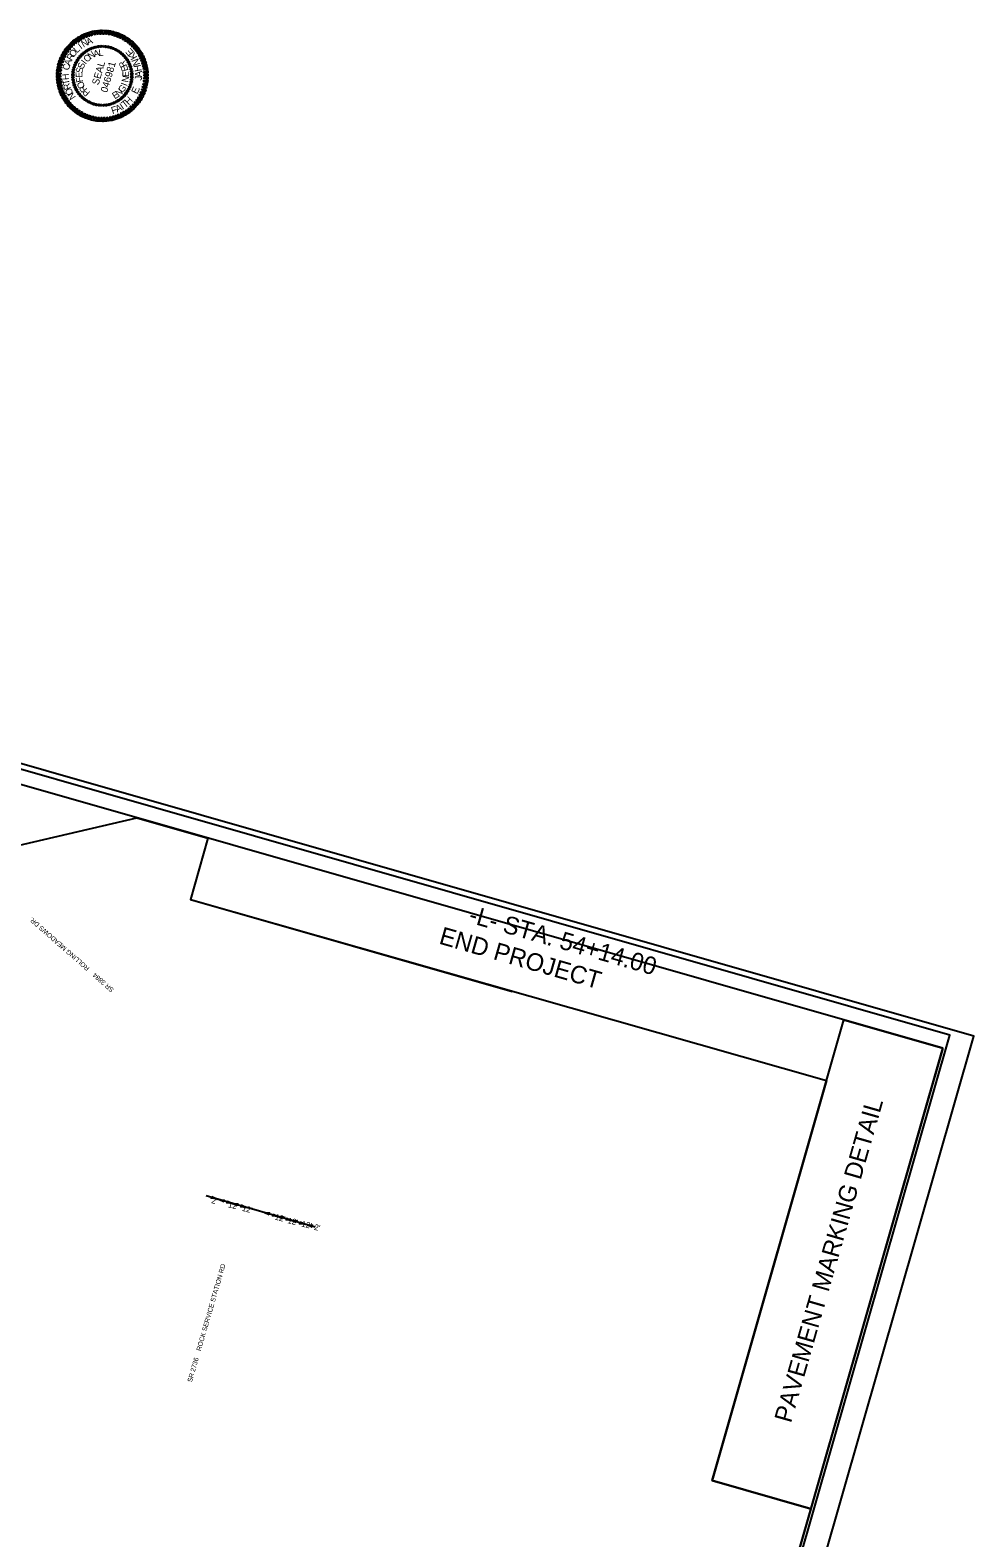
# Model space of a CAD drawing. Extents: x 2096990 to 2098506, y 687712 to 690186.
# Drawn here: x 2097704 to 2098506, y 688904 to 690186 of the extents above; entities that cross this region are included whole.
import ezdxf

# ---------------------------------------------------------------- set-up
doc = ezdxf.new("R2010")
doc.units = 0
for name, color, linetype in [('Default', 7, 'Continuous'), ('Matchline', 7, 'Continuous'), ('Matchline Text', 7, 'Continuous'), ('Sheet Layout Plan Border', 7, 'Continuous'), ('Sheet PE Seal Cell', 7, 'Continuous'), ('Sheet Plan CELL', 7, 'Continuous'), ('Sheet Plot Border Inside CELL', 7, 'Continuous'), ('Sheet Plot Border Outside CELL', 7, 'Continuous'), ('Text', 7, 'Continuous')]:
    doc.layers.add(name, color=color, linetype=linetype)

msp = doc.modelspace()

# ---------------------------------------------------------------- linework, layer by layer
at = {"layer": 'Default'}
msp.add_line((2097946.4, 689168), (2097853.6, 689194.6), dxfattribs=at)
for points in [[(2097858.4, 689194), (2097862.5, 689192), (2097858, 689192.5), (2097858.7, 689193.1)], [(2097868.6, 689189.4), (2097864.5, 689191.4), (2097869.1, 689191), (2097868.3, 689190.3)], [(2097871.9, 689190.1), (2097876, 689188.1), (2097871.4, 689188.6), (2097872.2, 689189.2)], [(2097880.1, 689186.2), (2097876, 689188.1), (2097880.6, 689187.7), (2097879.8, 689187.1)], [(2097883.6, 689186.8), (2097887.7, 689184.8), (2097883.1, 689185.3), (2097883.9, 689185.9)], [(2097907.2, 689178.5), (2097903.1, 689180.5), (2097907.6, 689180), (2097906.9, 689179.4)], [(2097910.6, 689179.1), (2097914.7, 689177.1), (2097910.2, 689177.6), (2097910.9, 689178.2)], [(2097918.7, 689175.1), (2097914.6, 689177.1), (2097919.2, 689176.6), (2097918.4, 689176)], [(2097922.1, 689175.7), (2097926.3, 689173.7), (2097921.7, 689174.2), (2097922.5, 689174.8)], [(2097930.2, 689171.8), (2097926.1, 689173.8), (2097930.7, 689173.3), (2097929.9, 689172.7)], [(2097933.7, 689172.4), (2097937.8, 689170.4), (2097933.2, 689170.9), (2097934, 689171.5)], [(2097943.7, 689168), (2097939.6, 689169.9), (2097944.2, 689169.5), (2097943.4, 689168.9)]]:
    msp.add_lwpolyline(points, close=True, dxfattribs=at)
at = {"layer": 'Matchline'}
msp.add_line((2097840.3, 689446.6), (2098113.9, 689368.3), dxfattribs=at)
at = {"layer": 'Sheet Layout Plan Border'}
msp.add_lwpolyline([(2098367.9, 688928.4), (2098117.8, 688054.5), (2097561.3, 688075.8), (2097494.5, 688123.8), (2097678.9, 688821), (2097441.6, 689082.4), (2097413, 689407.6), (2097643.8, 689341.5), (2097686.6, 689490.9), (2097794.8, 689516.3), (2097855.1, 689499), (2097840.3, 689446.6), (2098381.2, 689292.7), (2098283.8, 688952.5)], close=True, dxfattribs=at)
at = {"layer": 'Sheet PE Seal Cell'}
for p, q in [((2097748.3, 690165.8), (2097748.3, 690165.8)), ((2097750, 690167.2), (2097750, 690167.2)), ((2097751.8, 690168.5), (2097751.8, 690168.5)), ((2097753.6, 690169.6), (2097753.6, 690169.6)), ((2097755.6, 690170.6), (2097755.6, 690170.6)), ((2097757.6, 690171.3), (2097757.6, 690171.3)), ((2097759.8, 690171.9), (2097759.8, 690171.9)), ((2097761.9, 690172.3), (2097761.9, 690172.3)), ((2097764.1, 690172.5), (2097764.1, 690172.5)), ((2097766.3, 690172.5), (2097766.3, 690172.5)), ((2097768.5, 690172.3), (2097768.5, 690172.3)), ((2097770.6, 690172), (2097770.6, 690172)), ((2097772.8, 690171.5), (2097772.8, 690171.5)), ((2097774.8, 690170.7), (2097774.8, 690170.7)), ((2097776.8, 690169.8), (2097776.8, 690169.8)), ((2097778.7, 690168.8), (2097778.7, 690168.8)), ((2097780.5, 690167.5), (2097780.5, 690167.5)), ((2097782.2, 690166.1), (2097782.2, 690166.1)), ((2097783.8, 690164.6), (2097783.8, 690164.6)), ((2097740.9, 690152.7), (2097740.9, 690152.7)), ((2097741.4, 690154.8), (2097741.4, 690154.8)), ((2097742.2, 690156.9), (2097742.2, 690156.9)), ((2097743.1, 690158.8), (2097743.1, 690158.8)), ((2097744.1, 690160.7), (2097744.1, 690160.7)), ((2097745.4, 690162.6), (2097745.4, 690162.6)), ((2097746.8, 690164.2), (2097746.8, 690164.2)), ((2097785.2, 690162.9), (2097785.2, 690162.9)), ((2097786.5, 690161.1), (2097786.5, 690161.1)), ((2097787.6, 690159.3), (2097787.6, 690159.3)), ((2097788.6, 690157.3), (2097788.6, 690157.3)), ((2097789.3, 690155.2), (2097789.3, 690155.2)), ((2097789.9, 690153.1), (2097789.9, 690153.1)), ((2097740.3, 690148.3), (2097740.3, 690148.3)), ((2097740.3, 690146.1), (2097740.3, 690146.1)), ((2097740.6, 690150.5), (2097740.6, 690150.5)), ((2097740.6, 690144), (2097740.6, 690144)), ((2097741, 690141.8), (2097741, 690141.8)), ((2097741.6, 690139.7), (2097741.6, 690139.7)), ((2097765.4, 690147.5), (2097765.4, 690147.5)), ((2097789.4, 690140.1), (2097789.4, 690140.1)), ((2097790, 690142.2), (2097790, 690142.2)), ((2097790.3, 690150.9), (2097790.3, 690150.9)), ((2097790.3, 690144.4), (2097790.3, 690144.4)), ((2097790.5, 690148.8), (2097790.5, 690148.8)), ((2097790.5, 690146.6), (2097790.5, 690146.6)), ((2097742.3, 690137.6), (2097742.3, 690137.6)), ((2097743.3, 690135.6), (2097743.3, 690135.6)), ((2097744.4, 690133.8), (2097744.4, 690133.8)), ((2097745.7, 690132), (2097745.7, 690132)), ((2097747.1, 690130.3), (2097747.1, 690130.3)), ((2097748.7, 690128.8), (2097748.7, 690128.8)), ((2097750.3, 690127.4), (2097750.3, 690127.4)), ((2097752.2, 690126.1), (2097752.2, 690126.1)), ((2097779.1, 690126.4), (2097779.1, 690126.4)), ((2097780.9, 690127.7), (2097780.9, 690127.7)), ((2097782.6, 690129.1), (2097782.6, 690129.1)), ((2097784.1, 690130.7), (2097784.1, 690130.7)), ((2097785.5, 690132.3), (2097785.5, 690132.3)), ((2097786.8, 690134.2), (2097786.8, 690134.2)), ((2097787.8, 690136.1), (2097787.8, 690136.1)), ((2097788.7, 690138), (2097788.7, 690138)), ((2097754, 690125.1), (2097754, 690125.1)), ((2097756, 690124.2), (2097756, 690124.2)), ((2097758.1, 690123.4), (2097758.1, 690123.4)), ((2097760.2, 690122.9), (2097760.2, 690122.9)), ((2097762.4, 690122.6), (2097762.4, 690122.6)), ((2097764.6, 690122.4), (2097764.6, 690122.4)), ((2097766.8, 690122.4), (2097766.8, 690122.4)), ((2097768.9, 690122.6), (2097768.9, 690122.6)), ((2097771.1, 690123), (2097771.1, 690123)), ((2097773.2, 690123.6), (2097773.2, 690123.6)), ((2097775.2, 690124.3), (2097775.2, 690124.3)), ((2097777.2, 690125.3), (2097777.2, 690125.3))]:
    msp.add_line(p, q, dxfattribs=at)
for points in [[(2097742.6, 690174.6), (2097740.3, 690177.1), (2097741.7, 690178), (2097743.5, 690175.5)], [(2097744.6, 690176.1), (2097742.5, 690178.7), (2097743.9, 690179.6), (2097745.6, 690176.9)], [(2097746.6, 690177.5), (2097744.7, 690180.2), (2097746.2, 690181), (2097747.6, 690178.2)], [(2097748.8, 690178.8), (2097747.1, 690181.5), (2097748.6, 690182.3), (2097749.8, 690179.3)], [(2097751, 690180), (2097749.5, 690182.8), (2097751.1, 690183.4), (2097752.2, 690180.4)], [(2097753.3, 690180.9), (2097752, 690183.8), (2097753.6, 690184.3), (2097754.4, 690181.2)], [(2097755.6, 690181.6), (2097754.5, 690184.6), (2097756.2, 690185.1), (2097756.8, 690182)], [(2097758.1, 690182.2), (2097757.2, 690185.4), (2097758.9, 690185.6), (2097759.2, 690182.5)], [(2097760.5, 690182.6), (2097759.8, 690185.8), (2097761.5, 690186), (2097761.7, 690182.8)], [(2097763, 690182.8), (2097762.6, 690186.1), (2097764.2, 690186.2), (2097764.1, 690183)], [(2097765.5, 690182.9), (2097765.3, 690186.3), (2097766.9, 690186.1), (2097766.6, 690183)], [(2097768, 690182.8), (2097767.9, 690186.1), (2097769.6, 690185.9), (2097769.1, 690182.8)], [(2097770.4, 690182.6), (2097770.6, 690185.9), (2097772.3, 690185.6), (2097771.6, 690182.5)], [(2097772.8, 690182.2), (2097773.3, 690185.5), (2097775, 690185.1), (2097774, 690182)], [(2097775.2, 690181.6), (2097776, 690184.7), (2097777.6, 690184.3), (2097776.4, 690181.2)], [(2097777.6, 690180.8), (2097778.6, 690183.9), (2097780.1, 690183.4), (2097778.7, 690180.4)], [(2097779.8, 690179.9), (2097781, 690182.9), (2097782.6, 690182.3), (2097780.9, 690179.4)], [(2097782.2, 690178.9), (2097783.4, 690181.7), (2097784.9, 690180.9), (2097783.1, 690178.2)], [(2097784.3, 690177.6), (2097785.8, 690180.4), (2097787.3, 690179.6), (2097785.2, 690176.9)], [(2097786.4, 690176.2), (2097788.1, 690178.9), (2097789.4, 690177.9), (2097787.3, 690175.4)], [(2097733.5, 690162.9), (2097730.6, 690164.2), (2097731.3, 690165.8), (2097734, 690164)], [(2097734.7, 690165.2), (2097731.8, 690166.6), (2097732.6, 690168.1), (2097735.3, 690166.2)], [(2097736, 690167.4), (2097733.3, 690168.9), (2097734.2, 690170.3), (2097736.7, 690168.3)], [(2097737.5, 690169.3), (2097734.8, 690171.2), (2097735.8, 690172.4), (2097738.2, 690170.3)], [(2097739, 690171.2), (2097736.6, 690173.2), (2097737.7, 690174.5), (2097739.9, 690172.1)], [(2097740.8, 690173.1), (2097738.4, 690175.2), (2097739.6, 690176.4), (2097741.6, 690173.8)], [(2097788.2, 690174.6), (2097790.2, 690177.3), (2097791.5, 690176.1), (2097789.2, 690173.8)], [(2097790.2, 690173), (2097792.2, 690175.4), (2097793.4, 690174.3), (2097790.9, 690172.2)], [(2097791.9, 690171.3), (2097794.1, 690173.6), (2097795.2, 690172.2), (2097792.6, 690170.3)], [(2097793.4, 690169.3), (2097795.8, 690171.4), (2097796.9, 690170.1), (2097794.2, 690168.4)], [(2097794.8, 690167.3), (2097797.4, 690169.3), (2097798.4, 690167.9), (2097795.5, 690166.4)], [(2097796.2, 690165.1), (2097798.9, 690167), (2097799.6, 690165.5), (2097796.7, 690164.1)], [(2097797.4, 690163.1), (2097800.1, 690164.6), (2097801, 690163.1), (2097797.8, 690161.9)], [(2097730.1, 690151.2), (2097726.8, 690151.3), (2097727.1, 690153), (2097730.3, 690152.4)], [(2097730.5, 690153.6), (2097727.2, 690154), (2097727.5, 690155.6), (2097730.7, 690154.8)], [(2097730.9, 690156.1), (2097727.7, 690156.7), (2097728.2, 690158.3), (2097731.3, 690157.2)], [(2097731.6, 690158.4), (2097728.5, 690159.3), (2097729, 690160.8), (2097732, 690159.5)], [(2097732.5, 690160.7), (2097729.4, 690161.8), (2097730.1, 690163.3), (2097733, 690161.8)], [(2097798.3, 690160.7), (2097801.2, 690162.1), (2097801.9, 690160.5), (2097798.7, 690159.6)], [(2097799.3, 690158.5), (2097802.2, 690159.5), (2097802.8, 690158), (2097799.5, 690157.2)], [(2097799.9, 690156), (2097803, 690157), (2097803.3, 690155.3), (2097800.2, 690154.9)], [(2097800.4, 690153.6), (2097803.6, 690154.4), (2097803.8, 690152.7), (2097800.6, 690152.4)], [(2097730, 690148.8), (2097726.7, 690148.6), (2097726.8, 690150.3), (2097730, 690149.8)], [(2097729.9, 690146.3), (2097726.7, 690146), (2097726.7, 690147.6), (2097729.9, 690147.4)], [(2097730, 690143.7), (2097726.9, 690143.2), (2097726.7, 690144.9), (2097730.1, 690145)], [(2097730.4, 690141.3), (2097727.3, 690140.5), (2097727.1, 690142.2), (2097730.3, 690142.5)], [(2097731, 690138.9), (2097727.9, 690137.9), (2097727.6, 690139.6), (2097730.7, 690140)], [(2097800.4, 690141.3), (2097803.6, 690140.9), (2097803.3, 690139.3), (2097800.2, 690140.1)], [(2097800.8, 690143.7), (2097804.1, 690143.6), (2097803.7, 690141.9), (2097800.6, 690142.5)], [(2097800.8, 690151.2), (2097804, 690151.7), (2097804.1, 690150), (2097800.8, 690149.9)], [(2097800.9, 690146.1), (2097804.2, 690146.3), (2097804.1, 690144.6), (2097800.8, 690145.1)], [(2097800.9, 690148.6), (2097804.1, 690148.9), (2097804.1, 690147.3), (2097801, 690147.5)], [(2097731.6, 690136.4), (2097728.6, 690135.4), (2097728.1, 690136.9), (2097731.3, 690137.7)], [(2097732.5, 690134.2), (2097729.6, 690132.8), (2097729, 690134.4), (2097732.2, 690135.3)], [(2097733.5, 690131.8), (2097730.7, 690130.3), (2097729.9, 690131.8), (2097733, 690133)], [(2097734.7, 690129.8), (2097732, 690127.9), (2097731.2, 690129.4), (2097734.1, 690130.8)], [(2097736, 690127.6), (2097733.4, 690125.6), (2097732.5, 690127), (2097735.4, 690128.5)], [(2097737.4, 690125.6), (2097735.1, 690123.5), (2097733.9, 690124.8), (2097736.7, 690126.5)], [(2097794.8, 690127.5), (2097797.6, 690126), (2097796.7, 690124.6), (2097794.2, 690126.6)], [(2097796.1, 690129.7), (2097799.1, 690128.3), (2097798.3, 690126.8), (2097795.6, 690128.7)], [(2097797.4, 690132), (2097800.3, 690130.7), (2097799.6, 690129.1), (2097796.9, 690130.9)], [(2097798.4, 690134.2), (2097801.5, 690133.1), (2097800.7, 690131.6), (2097797.9, 690133.1)], [(2097799.2, 690136.5), (2097802.4, 690135.6), (2097801.9, 690134.1), (2097798.9, 690135.4)], [(2097799.9, 690138.8), (2097803.1, 690138.2), (2097802.6, 690136.6), (2097799.6, 690137.7)], [(2097739, 690123.6), (2097736.7, 690121.3), (2097735.7, 690122.7), (2097738.3, 690124.6)], [(2097740.7, 690121.9), (2097738.7, 690119.5), (2097737.4, 690120.6), (2097739.9, 690122.7)], [(2097742.6, 690120.3), (2097740.7, 690117.6), (2097739.4, 690118.8), (2097741.7, 690121.1)], [(2097744.5, 690118.7), (2097742.7, 690116), (2097741.4, 690117), (2097743.6, 690119.5)], [(2097746.6, 690117.3), (2097745.1, 690114.5), (2097743.6, 690115.3), (2097745.7, 690118)], [(2097748.7, 690116), (2097747.5, 690113.2), (2097745.9, 690114), (2097747.8, 690116.7)], [(2097751, 690115), (2097749.9, 690112), (2097748.3, 690112.6), (2097749.9, 690115.5)], [(2097753.3, 690114.1), (2097752.3, 690111), (2097750.7, 690111.5), (2097752.1, 690114.5)], [(2097755.7, 690113.3), (2097754.9, 690110.2), (2097753.3, 690110.6), (2097754.5, 690113.7)], [(2097775.2, 690113.3), (2097776.3, 690110.3), (2097774.6, 690109.8), (2097774.1, 690112.9)], [(2097777.6, 690114), (2097778.9, 690111.1), (2097777.2, 690110.6), (2097776.5, 690113.7)], [(2097779.8, 690114.9), (2097781.4, 690112.1), (2097779.8, 690111.5), (2097778.7, 690114.5)], [(2097782.1, 690116.1), (2097783.7, 690113.4), (2097782.2, 690112.6), (2097781.1, 690115.6)], [(2097784.2, 690117.4), (2097786.2, 690114.7), (2097784.7, 690113.9), (2097783.2, 690116.7)], [(2097786.2, 690118.8), (2097788.4, 690116.2), (2097787, 690115.3), (2097785.3, 690118)], [(2097788.2, 690120.3), (2097790.6, 690117.8), (2097789.2, 690116.9), (2097787.4, 690119.4)], [(2097790.1, 690121.8), (2097792.5, 690119.7), (2097791.2, 690118.5), (2097789.2, 690121.1)], [(2097791.8, 690123.7), (2097794.3, 690121.7), (2097793.2, 690120.4), (2097791, 690122.8)], [(2097793.4, 690125.6), (2097796.1, 690123.7), (2097795.1, 690122.5), (2097792.7, 690124.6)], [(2097758.1, 690112.7), (2097757.6, 690109.4), (2097755.9, 690109.8), (2097756.9, 690112.9)], [(2097760.5, 690112.3), (2097760.2, 690109), (2097758.6, 690109.3), (2097759.3, 690112.4)], [(2097762.9, 690112.1), (2097762.9, 690108.8), (2097761.2, 690109), (2097761.8, 690112.1)], [(2097765.4, 690112), (2097765.6, 690108.6), (2097763.9, 690108.8), (2097764.3, 690111.9)], [(2097767.9, 690112.1), (2097768.3, 690108.8), (2097766.7, 690108.7), (2097766.8, 690111.9)], [(2097770.4, 690112.3), (2097771, 690109.1), (2097769.3, 690108.9), (2097769.2, 690112.1)], [(2097772.7, 690112.7), (2097773.7, 690109.5), (2097772, 690109.3), (2097771.7, 690112.4)]]:
    msp.add_lwpolyline(points, close=True, dxfattribs=at)
for centre, major_axis in [((2097746.8, 690164.2), (-0.535, 0.482)), ((2097748.3, 690165.8), (-0.491, 0.526)), ((2097750, 690167.2), (-0.444, 0.567)), ((2097751.8, 690168.5), (-0.392, 0.604)), ((2097753.6, 690169.6), (-0.338, 0.636)), ((2097755.6, 690170.5), (-0.282, 0.663)), ((2097757.7, 690171.3), (-0.223, 0.685)), ((2097759.8, 690171.9), (-0.162, 0.701)), ((2097761.9, 690172.3), (-0.101, 0.713)), ((2097764.1, 690172.5), (-0.038, 0.719)), ((2097766.3, 690172.5), (0.025, 0.72)), ((2097768.5, 690172.3), (0.087, 0.715)), ((2097770.6, 690172), (0.149, 0.704)), ((2097772.8, 690171.4), (0.21, 0.689)), ((2097774.8, 690170.7), (0.269, 0.668)), ((2097776.8, 690169.8), (0.327, 0.642)), ((2097778.7, 690168.7), (0.381, 0.611)), ((2097780.5, 690167.5), (0.433, 0.575)), ((2097782.2, 690166.1), (0.482, 0.535)), ((2097783.8, 690164.6), (0.526, 0.491)), ((2097740.9, 690152.7), (-0.704, 0.149)), ((2097741.4, 690154.8), (-0.689, 0.21)), ((2097742.2, 690156.8), (-0.668, 0.269)), ((2097743.1, 690158.8), (-0.642, 0.327)), ((2097744.2, 690160.7), (-0.611, 0.381)), ((2097745.4, 690162.5), (-0.575, 0.433)), ((2097785.2, 690162.9), (0.567, 0.444)), ((2097786.5, 690161.1), (0.604, 0.392)), ((2097787.6, 690159.2), (0.636, 0.338)), ((2097788.5, 690157.3), (0.663, 0.282)), ((2097789.3, 690155.2), (0.685, 0.223)), ((2097789.9, 690153.1), (0.701, 0.162)), ((2097790.3, 690151), (0.713, 0.101)), ((2097740.4, 690148.3), (-0.72, 0.025)), ((2097740.4, 690146.1), (-0.719, -0.038)), ((2097740.5, 690150.5), (-0.715, 0.087)), ((2097740.6, 690143.9), (-0.713, -0.101)), ((2097741, 690141.8), (-0.701, -0.162)), ((2097741.6, 690139.7), (-0.685, -0.223)), ((2097788.7, 690138.1), (0.668, -0.269)), ((2097789.4, 690140.1), (0.689, -0.21)), ((2097790, 690142.2), (0.704, -0.149)), ((2097790.3, 690144.4), (0.715, -0.087)), ((2097790.5, 690148.8), (0.719, 0.038)), ((2097790.5, 690146.6), (0.72, -0.025)), ((2097742.3, 690137.6), (-0.663, -0.282)), ((2097743.3, 690135.7), (-0.636, -0.338)), ((2097744.4, 690133.8), (-0.604, -0.392)), ((2097745.7, 690132), (-0.567, -0.444)), ((2097747.1, 690130.3), (-0.526, -0.491)), ((2097748.7, 690128.8), (-0.482, -0.535)), ((2097750.3, 690127.4), (-0.433, -0.575)), ((2097752.2, 690126.2), (-0.381, -0.611)), ((2097777.2, 690125.3), (0.338, -0.636)), ((2097779.1, 690126.4), (0.392, -0.604)), ((2097780.9, 690127.7), (0.444, -0.567)), ((2097782.5, 690129.1), (0.491, -0.526)), ((2097784.1, 690130.7), (0.535, -0.482)), ((2097785.5, 690132.4), (0.575, -0.433)), ((2097786.7, 690134.2), (0.611, -0.381)), ((2097787.8, 690136.1), (0.642, -0.327)), ((2097754.1, 690125.1), (-0.327, -0.642)), ((2097756, 690124.2), (-0.269, -0.668)), ((2097758.1, 690123.5), (-0.21, -0.689)), ((2097760.2, 690122.9), (-0.149, -0.704)), ((2097762.4, 690122.6), (-0.087, -0.715)), ((2097764.6, 690122.4), (-0.025, -0.72)), ((2097766.8, 690122.4), (0.038, -0.719)), ((2097768.9, 690122.6), (0.101, -0.713)), ((2097771.1, 690123), (0.162, -0.701)), ((2097773.2, 690123.6), (0.223, -0.685)), ((2097775.2, 690124.4), (0.282, -0.663))]:
    msp.add_ellipse(centre, major_axis=major_axis, ratio=0.999708, dxfattribs=at)
at = {"layer": 'Sheet Plan CELL'}
for p, q in [((2098480.1, 689320.1), (2097470.6, 689609.1)), ((2098067.3, 687878), (2098480.1, 689320.1))]:
    msp.add_line(p, q, dxfattribs=at)
msp.add_lwpolyline([(2098480.1, 689320.1), (2098367.9, 688928.4), (2098283.8, 688952.5), (2098396, 689344.2)], close=True, dxfattribs=at)
at = {"layer": 'Sheet Plot Border Inside CELL'}
msp.add_lwpolyline([(2098027.5, 687729.8), (2098485.9, 689331.4), (2097471.7, 689621.8), (2097013.2, 688020.1)], close=True, dxfattribs=at)
at = {"layer": 'Sheet Plot Border Outside CELL'}
msp.add_lwpolyline([(2098043.1, 687711.8), (2098506.4, 689330.3), (2097453.7, 689631.6), (2096990.4, 688013.1)], close=True, dxfattribs=at)

# ---------------------------------------------------------------- texts
at = {"layer": 'Matchline Text'}
for s, p in [('-L- STA. 54+14.00', (2098076, 689427.4)), ('END PROJECT', (2098050.9, 689409.3))]:
    msp.add_text(s, height=15, rotation=343.9917, dxfattribs=at).set_placement(p)
at = {"layer": 'Sheet PE Seal Cell'}
for s, height, rotation, p in [('N', 5.64, 29.8448, (2097749.5, 690171.4)), ('A', 5.64, 22.643, (2097753.2, 690173.4)), ('R', 5.64, 58.647, (2097739.4, 690159.8)), ('O', 5.64, 51.4471, (2097741, 690162.8)), ('L', 5.64, 44.2468, (2097744, 690166.5)), ('I', 5.64, 37.046, (2097747.4, 690169.8)), ('O', 5.64, 43.8594, (2097752.5, 690158.5)), ('N', 5.64, 34.5025, (2097755.3, 690161.2)), ('A', 5.64, 15.7862, (2097758.6, 690163.2)), ('L', 5.64, 6.4267, (2097762.5, 690164.2)), ('E', 6, 129.5189, (2097792.7, 690167.3)), ('K', 6, 121.235, (2097795.3, 690163.2)), ('C', 5.64, 80.2458, (2097737.2, 690151.9)), ('A', 5.64, 73.0462, (2097738, 690155.8)), ('S', 5.64, 81.2815, (2097748.5, 690149.4)), ('S', 5.64, 71.9263, (2097749.4, 690152.9)), ('I', 5.64, 53.2155, (2097751.3, 690156.8)), ('SEAL', 6, 74.0259, (2097762.2, 690139.2)), ('046981', 6, 74.0259, (2097769.6, 690132.8)), ('R', 5.64, 116.5073, (2097786.4, 690156.1)), ('E', 5.64, 107.15, (2097787.7, 690152.1)), ('N', 6, 110.5092, (2097797.7, 690157.3)), ('H', 6, 100.5252, (2097798.9, 690151.6)), ('A', 6, 91.6849, (2097799.2, 690146.4)), ('H', 5.64, 94.6454, (2097737.1, 690144.1)), ('T', 5.64, 101.8457, (2097737.8, 690140.5)), ('R', 5.64, 109.0464, (2097738.9, 690136.6)), ('E', 5.64, 90.637, (2097748.5, 690145.8)), ('F', 5.64, 99.9929, (2097749.1, 690142.3)), ('O', 5.64, 118.7071, (2097751, 690138.3)), ('R', 5.64, 128.0655, (2097752.9, 690136)), ('G', 5.64, 51.0161, (2097782.6, 690132.6)), ('I', 5.64, 69.7271, (2097786.2, 690138.3)), ('N', 5.64, 79.0823, (2097787.3, 690141.5)), ('E', 5.64, 88.4377, (2097788.1, 690146.4)), ('J', 6, 86.427, (2097798.9, 690143.3)), ('O', 5.64, 116.2476, (2097741, 690132.5)), ('N', 5.64, 123.4494, (2097743.1, 690129.4)), ('P', 5.64, 137.4248, (2097755.5, 690133.5)), ('E', 5.64, 32.3028, (2097776, 690127.4)), ('N', 5.64, 41.6598, (2097779.4, 690129.5)), ('T', 6, 38.099, (2097784.6, 690119.7)), ('H', 6, 44.8992, (2097787.8, 690122.1)), ('E', 6, 65.0836, (2097795.1, 690131.4)), ('.', 6, 72.1929, (2097796.9, 690135.2)), ('F', 6, 18.4401, (2097774.1, 690114.8)), ('A', 6, 25.4567, (2097778.1, 690116.1)), ('I', 6, 34.297, (2097782.7, 690118.4))]:
    msp.add_text(s, height=height, rotation=rotation, dxfattribs=at).set_placement(p)
at = {"layer": 'Text'}
for s, height, rotation, p in [('SR 3884    ROLLING MEADOWS DR.   ', 4, 138.6959, (2097775.6, 689370.4)), ('PAVEMENT MARKING DETAIL', 15, 74.0259, (2098350.9, 689000.7)), ("2'", 5, 346.4452, (2097857.8, 689188.5)), ("12'", 5, 346.4452, (2097872, 689184.9)), ("12'", 5, 346.4452, (2097883.8, 689181.9)), ("12'", 5, 346.4452, (2097911.7, 689174.4)), ("12'", 5, 346.4452, (2097922.6, 689171.4)), ("12'", 5, 346.4452, (2097934.3, 689168.6)), ("2'", 5, 346.4452, (2097945.1, 689165.8)), ('SR 2736    ROCK SERVICE STATION RD   ', 4, 74.0259, (2097841.5, 689035.7))]:
    msp.add_text(s, height=height, rotation=rotation, dxfattribs=at).set_placement(p)

doc.saveas('drawing.dxf')
